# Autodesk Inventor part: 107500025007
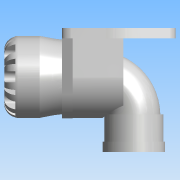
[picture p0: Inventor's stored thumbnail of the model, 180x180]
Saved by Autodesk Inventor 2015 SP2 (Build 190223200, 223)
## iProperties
Created: 2017-01
Part Number: 107500025007
Material: PVC-Piping
Description: PLASSON WALL PLATE ELBOW 25X3/4" SERIES 1
Document SubType Name: Modeling
Designer: Кирилл
Mass: 122.736 g
Surface Area: 365.546 cm^2
Volume: 87.6688 cm^3
Density: 1.4 g/cm^3
Appearance: Smooth - White
Author: KIM
Author: naamad
Title: SR1-ELBOW-BRACKET-20-CAT
Organization: PLASSON
Sending System: PRO/ENGINEER BY PARAMETRIC TECHNOLOGY CORPORATION, 2014000
Preprocessor: PRO/ENGINEER BY PARAMETRIC TECHNOLOGY CORPORATION, 2014000
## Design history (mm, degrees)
derived "1075.ipt"
feature "Solid1::1075.ipt"
feature "Solid8::1075.ipt"
feature "Solid11::1075.ipt"
tag "TaggingFeature1"
body "Solid1"
body "Solid2"
body "Solid3"
other parameters: "d3" = 25, "d4" = 47, "d5" = 31.25, "d6" = 20.16, "d7" = 48, "d9" = 41.36, "d13" = 3.96, "d14" = 7.92, "d24" = 43, "d26" = 74, "d29" = 30.38742, "d31" = 0, "d32" = 0, "d39" = 6.3, "d41" = 6.3, "d42" = 0, "d44" = 360 deg, "d46" = 8 deg, "d47" = 8 deg, "d48" = 0.5, "d49" = 0.5, "d51" = 0, "d53" = 360 deg, "d55" = 0.25, "d61" = 2.5, "d65" = 5.48629, "d69" = 90 deg, "d71" = 4.658, "d72" = 0, "d73" = 0, "d74" = 5.5, "d78" = 28, "d79" = 39, "d80" = 98, "d81" = 6, "d82" = 0, "d83" = 6, "d84" = 0, "d87" = 27, "d88" = 0, "d89" = 27, "d90" = 0, "d91" = 28, "d93" = 98, "d94" = 39, "d95" = 6, "d96" = 0, "d98" = 6, "d99" = 0, "d100" = 4.5, "d101" = 19, "d102" = 29, "d103" = 0, "d105" = 0, "d107" = 0, "d108" = 24.117, "d109" = 4.8234, "d110" = 0.96468, "d111" = 18, "d112" = 21.6, "d113" = 21.7053, "d114" = 6, "d_" = 25, "Rp_" = 24.117, "E_" = 47, "l_" = 48, "l_2" = 18, "A_" = 74, "A_1" = 43, "A_2" = 28, "L_" = 78, "H_" = 98, "d30" = 33.7638, "d37" = 31.25, "d38" = 47, "d40" = 7.875
